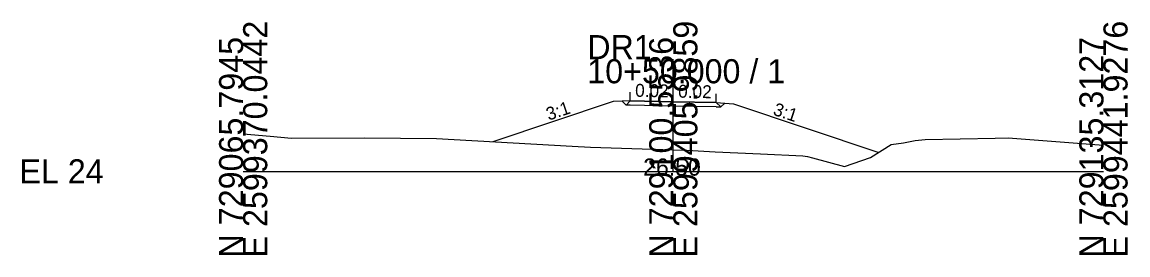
# Model space of a CAD drawing. Extents: x -26 to 1162, y -10 to 9515.
# Drawn here: x -25.7 to 102.8, y 2490.3 to 2517.3 of the extents above; entities that cross this region are included whole.
import ezdxf

# ---------------------------------------------------------------- set-up
doc = ezdxf.new("R2010")
doc.units = 0
for name, color, linetype in [('Exist Cross Section Cell', 7, 'Continuous'), ('Exist XS Center Line Elevation Label', 7, 'Continuous'), ('Exist XS Ground Line', 7, 'Continuous'), ('Prop XS Ditch Slope Text', 7, 'Continuous'), ('Prop XS Dump Level', 7, 'Continuous'), ('Prop XS EOT Tick Mark', 7, 'Continuous'), ('Prop XS Finish Grade', 7, 'Continuous'), ('Prop XS Finish Grade Earthwork', 7, 'Continuous'), ('Prop XS Finish Grade Pavement', 7, 'Continuous'), ('Prop XS Pvmt Edge Slope', 7, 'Continuous'), ('Prop XS SE Text', 7, 'Continuous'), ('Prop XS Subgrade Earthwork', 7, 'Continuous')]:
    doc.layers.add(name, color=color, linetype=linetype)

msp = doc.modelspace()

# ---------------------------------------------------------------- linework, layer by layer
at = {"layer": 'Exist Cross Section Cell'}
for p, q in [((50, 2500), (50, 2513.02)), ((0, 2500), (50, 2500)), ((50, 2500), (100, 2500))]:
    msp.add_line(p, q, dxfattribs=at)
at = {"layer": 'Exist XS Ground Line'}
msp.add_lwpolyline([(0, 2504.34), (3.13, 2504.09), (5.61, 2503.85), (14.11, 2503.9), (22.48, 2503.8), (38.25, 2502.94), (40.39, 2502.8), (50, 2502.5), (51.59, 2502.45), (54.85, 2502.25), (60.12, 2502.02), (65.05, 2501.81), (65.61, 2501.71), (66.17, 2501.57), (69.9, 2500.58), (72.94, 2501.61), (75.32, 2503.11), (76.76, 2503.32), (78.11, 2503.57), (79.27, 2503.7), (87.43, 2503.84), (88.94, 2503.91), (100, 2503.04)], dxfattribs=at)
at = {"layer": 'Prop XS Dump Level'}
for p, q in [((50, 2508.08), (45, 2508.18)), ((45, 2508.18), (50, 2508.08)), ((55, 2507.98), (50, 2508.08)), ((50, 2508.08), (55, 2507.98))]:
    msp.add_line(p, q, dxfattribs=at)
at = {"layer": 'Prop XS EOT Tick Mark'}
for p, q in [((45, 2508.18), (45, 2509.18)), ((55, 2507.98), (55, 2508.98))]:
    msp.add_line(p, q, dxfattribs=at)
at = {"layer": 'Prop XS Finish Grade'}
for p, q in [((45, 2508.18), (44.06, 2508.14)), ((55, 2507.98), (55.98, 2507.9))]:
    msp.add_line(p, q, dxfattribs=at)
at = {"layer": 'Prop XS Finish Grade Earthwork'}
for p, q in [((43, 2508.1), (29.04, 2503.44)), ((44.06, 2508.14), (43, 2508.1)), ((55.98, 2507.9), (57, 2507.82)), ((57, 2507.82), (73.88, 2502.2))]:
    msp.add_line(p, q, dxfattribs=at)
at = {"layer": 'Prop XS Finish Grade Pavement'}
for p, q in [((45, 2508.18), (50, 2508.08)), ((50, 2508.08), (55, 2507.98))]:
    msp.add_line(p, q, dxfattribs=at)
at = {"layer": 'Prop XS Pvmt Edge Slope'}
for p, q in [((44.06, 2508.14), (44.51, 2507.69)), ((45, 2508.18), (44.51, 2507.69)), ((55, 2507.98), (55.51, 2507.47)), ((55.98, 2507.9), (55.51, 2507.47))]:
    msp.add_line(p, q, dxfattribs=at)
at = {"layer": 'Prop XS Subgrade Earthwork'}
for p, q in [((44.51, 2507.69), (44.06, 2508.14)), ((44.51, 2507.69), (44.06, 2508.14)), ((45, 2507.68), (44.51, 2507.69)), ((50, 2507.58), (45, 2507.68)), ((55.51, 2507.47), (55.98, 2507.9)), ((55.51, 2507.47), (55.98, 2507.9)), ((55, 2507.48), (50, 2507.58)), ((55, 2507.48), (55.51, 2507.47))]:
    msp.add_line(p, q, dxfattribs=at)

# ---------------------------------------------------------------- texts
at = {"layer": 'Exist Cross Section Cell'}
for s, p in [('E 2599370.0442', (2.8, 2490)), ('E 2599405.9859', (52.8, 2490)), ('E 2599441.9276', (102.8, 2490)), ('N 729065.7945', (0, 2490)), ('N 729100.5536', (50, 2490)), ('N 729135.3127', (100, 2490))]:
    msp.add_text(s, height=2.8, rotation=90, dxfattribs=at).set_placement(p)
for s, p in [('DR1', (40, 2513.02)), ('10+50.000 / 1', (40, 2510.22)), ('EL 24', (-26, 2498.6))]:
    msp.add_text(s, height=2.8, dxfattribs=at).set_placement(p)
at = {"layer": 'Exist XS Center Line Elevation Label'}
msp.add_text('26.50', height=2, dxfattribs=at).set_placement((46.5, 2499.5))
at = {"layer": 'Prop XS Ditch Slope Text'}
for rotation, p in [(18.4349, (35.51, 2505.88)), (341.5883, (61.5, 2506.59))]:
    msp.add_text('3:1', height=1.5, rotation=rotation, dxfattribs=at).set_placement(p)
at = {"layer": 'Prop XS Dump Level'}
for p in [(43, 2508.06), (57, 2507.78)]:
    msp.add_text('Case1', height=0.04, dxfattribs=at).set_placement(p)
at = {"layer": 'Prop XS SE Text'}
for p in [(45.55, 2508.66), (50.55, 2508.56)]:
    msp.add_text('0.02', height=1.5, rotation=358.8542, dxfattribs=at).set_placement(p)

doc.saveas('drawing.dxf')
